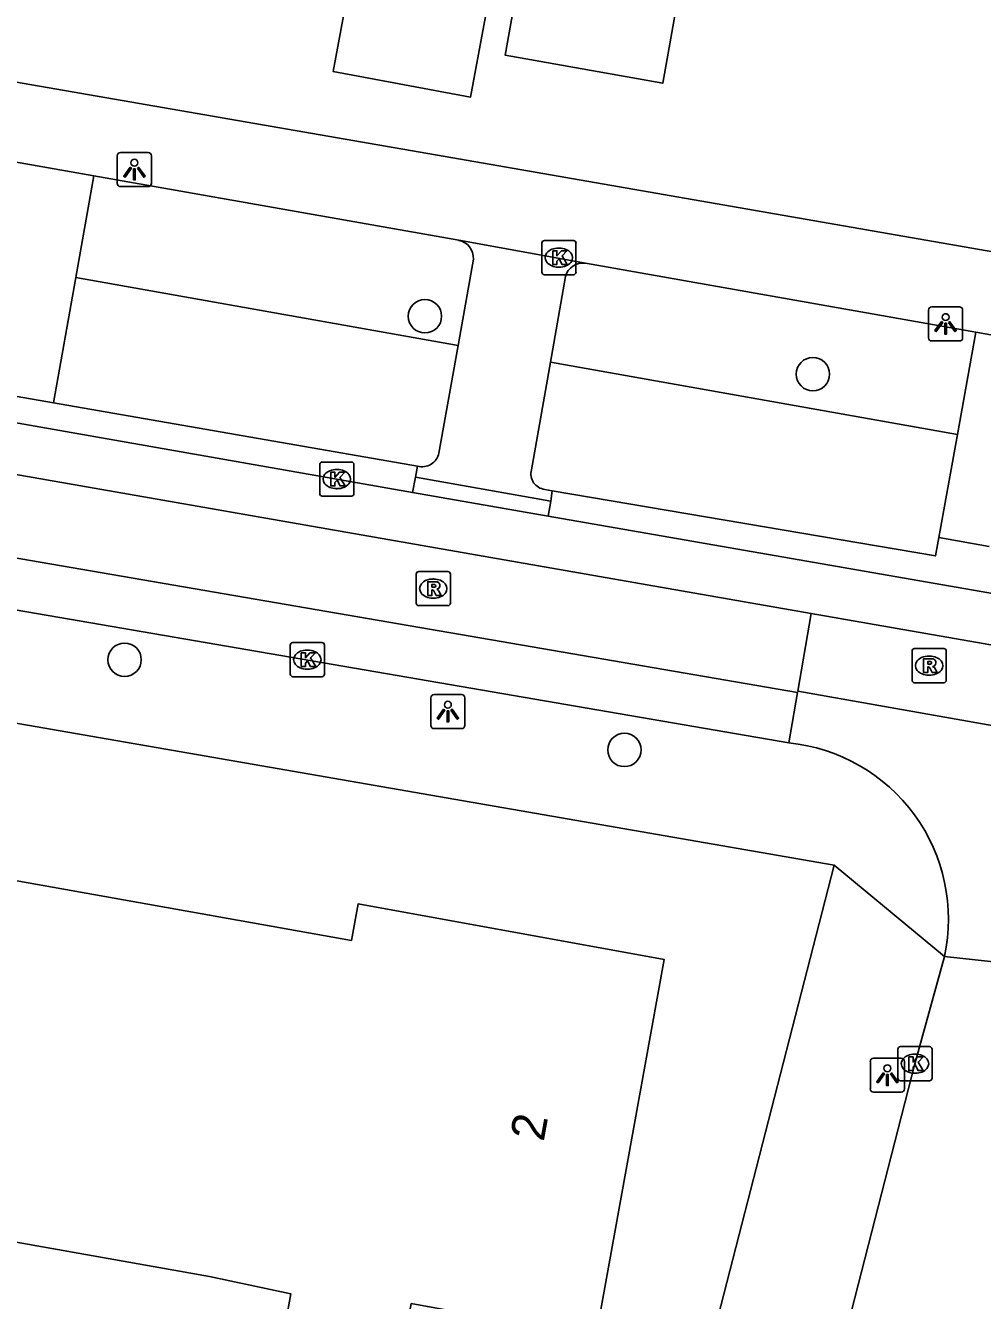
# Model space of a CAD drawing. Extents: x 163686 to 164493, y 382719 to 383870.
# Drawn here: x 163994.61 to 164022.62, y 383367.98 to 383405.27 of the extents above; entities that cross this region are included whole.
import ezdxf

# ---------------------------------------------------------------- set-up
doc = ezdxf.new("R2010")
doc.units = 0
for name, color, linetype in [('IMGEO_Boom', 7, 'Continuous'), ('IMGEO_Groenvoorziening', 7, 'Continuous'), ('IMGEO_Kolk', 7, 'Continuous'), ('IMGEO_Lichtpunt', 7, 'Continuous'), ('IMGEO_Pand', 7, 'Continuous'), ('IMGEO_Pand_nummerreeks', 7, 'Continuous'), ('IMGEO_Rijbaan_lokaal_open', 7, 'Continuous'), ('IMGEO_Rioolput', 7, 'Continuous'), ('IMGEO_Voetpad_open', 7, 'Continuous')]:
    doc.layers.add(name, color=color, linetype=linetype)

msp = doc.modelspace()

# ---------------------------------------------------------------- linework, layer by layer
at = {"layer": 'IMGEO_Boom'}
for centre in [(164006.301, 383396.766), (164017.654, 383395.071), (163997.512, 383386.717), (164012.139, 383384.08)]:
    msp.add_circle(centre, 0.489, dxfattribs=at)
at = {"layer": 'IMGEO_Groenvoorziening'}
for points in [[(163996.61, 383400.87), (163996.08, 383397.896)], [(163996.08, 383397.896), (163995.427, 383394.231)], [(164007.27, 383395.907), (163996.08, 383397.896)], [(164021.882, 383393.31), (164009.971, 383395.427)]]:
    msp.add_lwpolyline(points, dxfattribs=at)
at = {"layer": 'IMGEO_Kolk'}
for p, q in [((164009.72, 383398.055), (164009.72, 383398.907)), ((164009.795, 383398.981), (164010.647, 383398.981)), ((164010.721, 383398.907), (164010.721, 383398.055)), ((164010.208, 383398.761), (164010.233, 383398.761)), ((164010.231, 383398.201), (164010.206, 383398.201)), ((164010.647, 383397.981), (164009.795, 383397.981)), ((164003.298, 383392.502), (164004.15, 383392.502)), ((164003.223, 383391.576), (164003.223, 383392.428)), ((164003.711, 383392.282), (164003.736, 383392.282)), ((164004.224, 383392.428), (164004.224, 383391.576)), ((164004.15, 383391.502), (164003.298, 383391.502)), ((164003.734, 383391.722), (164003.709, 383391.722)), ((164002.359, 383386.295), (164002.359, 383387.147)), ((164002.434, 383387.221), (164003.286, 383387.221)), ((164002.847, 383387.001), (164002.872, 383387.001)), ((164003.36, 383387.147), (164003.36, 383386.295)), ((164003.286, 383386.221), (164002.434, 383386.221)), ((164002.87, 383386.441), (164002.845, 383386.441)), ((164020.14, 383374.476), (164020.14, 383375.328)), ((164020.215, 383375.402), (164021.067, 383375.402)), ((164021.141, 383375.328), (164021.141, 383374.476)), ((164020.628, 383375.182), (164020.653, 383375.182)), ((164020.651, 383374.622), (164020.626, 383374.622)), ((164021.067, 383374.402), (164020.215, 383374.402))]:
    msp.add_line(p, q, dxfattribs=at)
for points in [[(164009.72, 383398.055), (164009.72, 383398.907)], [(164009.795, 383398.981), (164010.647, 383398.981)], [(164010.721, 383398.907), (164010.721, 383398.055)], [(164010.041, 383398.681), (164010.164, 383398.681), (164010.164, 383398.53), (164010.294, 383398.681), (164010.458, 383398.681), (164010.312, 383398.53), (164010.465, 383398.281), (164010.313, 383398.281), (164010.228, 383398.445), (164010.164, 383398.378), (164010.164, 383398.281), (164010.041, 383398.281), (164010.041, 383398.681)], [(164010.647, 383397.981), (164009.795, 383397.981)], [(164003.298, 383392.502), (164004.15, 383392.502)], [(164003.223, 383391.576), (164003.223, 383392.428)], [(164003.544, 383392.202), (164003.667, 383392.202), (164003.667, 383392.051), (164003.797, 383392.202), (164003.961, 383392.202), (164003.815, 383392.051), (164003.968, 383391.802), (164003.816, 383391.802), (164003.731, 383391.966), (164003.667, 383391.899), (164003.667, 383391.802), (164003.544, 383391.802), (164003.544, 383392.202)], [(164004.224, 383392.428), (164004.224, 383391.576)], [(164004.15, 383391.502), (164003.298, 383391.502)], [(164002.359, 383386.295), (164002.359, 383387.147)], [(164002.434, 383387.221), (164003.286, 383387.221)], [(164002.68, 383386.921), (164002.803, 383386.921), (164002.803, 383386.77), (164002.933, 383386.921), (164003.097, 383386.921), (164002.951, 383386.77), (164003.104, 383386.521), (164002.952, 383386.521), (164002.867, 383386.685), (164002.803, 383386.618), (164002.803, 383386.521), (164002.68, 383386.521), (164002.68, 383386.921)], [(164003.36, 383387.147), (164003.36, 383386.295)], [(164003.286, 383386.221), (164002.434, 383386.221)], [(164020.14, 383374.476), (164020.14, 383375.328)], [(164020.215, 383375.402), (164021.067, 383375.402)], [(164021.141, 383375.328), (164021.141, 383374.476)], [(164020.461, 383375.102), (164020.584, 383375.102), (164020.584, 383374.951), (164020.714, 383375.102), (164020.878, 383375.102), (164020.732, 383374.951), (164020.885, 383374.702), (164020.733, 383374.702), (164020.648, 383374.866), (164020.584, 383374.799), (164020.584, 383374.702), (164020.461, 383374.702), (164020.461, 383375.102)], [(164021.067, 383374.402), (164020.215, 383374.402)]]:
    msp.add_lwpolyline(points, dxfattribs=at)
for centre, start, end in [((164009.797, 383398.905), 91.552, 178.448), ((164009.797, 383398.905), 91.552, 178.448), ((164010.645, 383398.905), 1.552, 88.448), ((164010.645, 383398.905), 1.552, 88.448), ((164009.797, 383398.057), 181.552, 268.448), ((164009.797, 383398.057), 181.552, 268.448), ((164010.645, 383398.057), 271.552, 358.448), ((164010.645, 383398.057), 271.552, 358.448), ((164003.3, 383392.426), 91.552, 178.448), ((164003.3, 383392.426), 91.552, 178.448), ((164004.148, 383392.426), 1.552, 88.448), ((164004.148, 383392.426), 1.552, 88.448), ((164003.3, 383391.578), 181.552, 268.448), ((164003.3, 383391.578), 181.552, 268.448), ((164004.148, 383391.578), 271.552, 358.448), ((164004.148, 383391.578), 271.552, 358.448), ((164002.436, 383387.145), 91.552, 178.448), ((164002.436, 383387.145), 91.552, 178.448), ((164003.284, 383387.145), 1.552, 88.448), ((164003.284, 383387.145), 1.552, 88.448), ((164002.436, 383386.297), 181.552, 268.448), ((164002.436, 383386.297), 181.552, 268.448), ((164003.284, 383386.297), 271.552, 358.448), ((164003.284, 383386.297), 271.552, 358.448), ((164020.217, 383375.326), 91.552, 178.448), ((164020.217, 383375.326), 91.552, 178.448), ((164021.065, 383375.326), 1.552, 88.448), ((164021.065, 383375.326), 1.552, 88.448), ((164020.217, 383374.478), 181.552, 268.448), ((164020.217, 383374.478), 181.552, 268.448), ((164021.065, 383374.478), 271.552, 358.448), ((164021.065, 383374.478), 271.552, 358.448)]:
    msp.add_arc(centre, 0.0765, start, end, dxfattribs=at)
for centre, major_axis, ratio, start_param, end_param in [((164010.207, 383398.481), (-0.387, 0.002), 0.722429, 4.712389, 7.853982), ((164010.232, 383398.481), (-0.39, 0.002), 0.717154, 1.570796, 4.712389), ((164003.71, 383392.002), (-0.387, 0.002), 0.722429, 4.712389, 7.853982), ((164003.735, 383392.002), (-0.39, 0.002), 0.717154, 1.570796, 4.712389), ((164002.846, 383386.721), (-0.387, 0.002), 0.722429, 4.712389, 7.853982), ((164002.871, 383386.721), (-0.39, 0.002), 0.717154, 1.570796, 4.712389), ((164020.627, 383374.902), (-0.387, 0.002), 0.722429, 4.712389, 7.853982), ((164020.652, 383374.902), (-0.39, 0.002), 0.717154, 1.570796, 4.712389)]:
    msp.add_ellipse(centre, major_axis=major_axis, ratio=ratio, start_param=start_param, end_param=end_param, dxfattribs=at)
at = {"layer": 'IMGEO_Lichtpunt'}
for p, q in [((163997.299, 383401.459), (163997.299, 383400.652)), ((163997.299, 383401.459), (163997.299, 383400.652)), ((163998.201, 383401.554), (163997.393, 383401.554)), ((163998.201, 383401.554), (163997.393, 383401.554)), ((163998.295, 383400.652), (163998.295, 383401.459)), ((163998.295, 383400.652), (163998.295, 383401.459)), ((163997.393, 383400.558), (163998.201, 383400.558)), ((163997.393, 383400.558), (163998.201, 383400.558)), ((164021.941, 383397.038), (164021.133, 383397.038)), ((164021.941, 383397.038), (164021.133, 383397.038)), ((164021.039, 383396.943), (164021.039, 383396.136)), ((164021.039, 383396.943), (164021.039, 383396.136)), ((164022.035, 383396.136), (164022.035, 383396.943)), ((164022.035, 383396.136), (164022.035, 383396.943)), ((164021.133, 383396.042), (164021.941, 383396.042)), ((164021.133, 383396.042), (164021.941, 383396.042)), ((164006.474, 383385.605), (164006.474, 383384.798)), ((164006.474, 383385.605), (164006.474, 383384.798)), ((164007.376, 383385.7), (164006.568, 383385.7)), ((164007.376, 383385.7), (164006.568, 383385.7)), ((164007.47, 383384.798), (164007.47, 383385.605)), ((164007.47, 383384.798), (164007.47, 383385.605)), ((164006.568, 383384.704), (164007.376, 383384.704)), ((164006.568, 383384.704), (164007.376, 383384.704)), ((164019.335, 383374.97), (164019.335, 383374.163)), ((164019.335, 383374.97), (164019.335, 383374.163)), ((164020.237, 383375.065), (164019.429, 383375.065)), ((164020.237, 383375.065), (164019.429, 383375.065)), ((164020.331, 383374.163), (164020.331, 383374.97)), ((164020.331, 383374.163), (164020.331, 383374.97)), ((164019.429, 383374.069), (164020.237, 383374.069)), ((164019.429, 383374.069), (164020.237, 383374.069))]:
    msp.add_line(p, q, dxfattribs=at)
for points in [[(163997.673, 383401.123), (163997.712, 383401.095), (163997.524, 383400.833), (163997.486, 383400.86), (163997.673, 383401.123)], [(163997.775, 383401.075), (163997.822, 383401.075), (163997.822, 383400.753), (163997.775, 383400.753), (163997.775, 383401.075)], [(163997.885, 383401.095), (163997.923, 383401.122), (163998.11, 383400.86), (163998.071, 383400.832), (163997.885, 383401.095)], [(164021.413, 383396.607), (164021.452, 383396.579), (164021.264, 383396.317), (164021.226, 383396.344), (164021.413, 383396.607)], [(164021.625, 383396.579), (164021.663, 383396.606), (164021.85, 383396.344), (164021.811, 383396.316), (164021.625, 383396.579)], [(164021.515, 383396.559), (164021.562, 383396.559), (164021.562, 383396.237), (164021.515, 383396.237), (164021.515, 383396.559)], [(164006.848, 383385.269), (164006.887, 383385.241), (164006.699, 383384.979), (164006.661, 383385.006), (164006.848, 383385.269)], [(164006.95, 383385.221), (164006.997, 383385.221), (164006.997, 383384.899), (164006.95, 383384.899), (164006.95, 383385.221)], [(164007.06, 383385.241), (164007.098, 383385.268), (164007.285, 383385.006), (164007.246, 383384.978), (164007.06, 383385.241)], [(164019.709, 383374.634), (164019.748, 383374.606), (164019.56, 383374.344), (164019.522, 383374.371), (164019.709, 383374.634)], [(164019.811, 383374.586), (164019.858, 383374.586), (164019.858, 383374.264), (164019.811, 383374.264), (164019.811, 383374.586)], [(164019.921, 383374.606), (164019.959, 383374.633), (164020.146, 383374.371), (164020.107, 383374.343), (164019.921, 383374.606)]]:
    msp.add_lwpolyline(points, dxfattribs=at)
for centre in [(163997.798, 383401.257), (164021.538, 383396.741), (164006.973, 383385.403), (164019.834, 383374.768)]:
    msp.add_circle(centre, 0.0994, dxfattribs=at)
for centre, start, end in [((163997.393, 383401.459), 90, 180), ((163997.393, 383401.459), 90, 180), ((163998.201, 383401.459), 0, 90), ((163998.201, 383401.459), 0, 90), ((163997.393, 383400.652), 180, 270), ((163997.393, 383400.652), 180, 270), ((163998.201, 383400.652), 270, 0), ((163998.201, 383400.652), 270, 360), ((164021.133, 383396.943), 90, 180), ((164021.133, 383396.943), 90, 180), ((164021.941, 383396.943), 0, 90), ((164021.941, 383396.943), 0, 90), ((164021.133, 383396.136), 180, 270), ((164021.133, 383396.136), 180, 270), ((164021.941, 383396.136), 270, 0), ((164021.941, 383396.136), 270, 360), ((164006.568, 383385.605), 90, 180), ((164006.568, 383385.605), 90, 180), ((164007.376, 383385.605), 0, 90), ((164007.376, 383385.605), 0, 90), ((164006.568, 383384.798), 180, 270), ((164006.568, 383384.798), 180, 270), ((164007.376, 383384.798), 270, 0), ((164007.376, 383384.798), 270, 360), ((164019.429, 383374.97), 90, 180), ((164019.429, 383374.97), 90, 180), ((164020.237, 383374.97), 0, 90), ((164020.237, 383374.97), 0, 90), ((164019.429, 383374.163), 180, 270), ((164019.429, 383374.163), 180, 270), ((164020.237, 383374.163), 270, 0), ((164020.237, 383374.163), 270, 360)]:
    msp.add_arc(centre, 0.0946, start, end, dxfattribs=at)
at = {"layer": 'IMGEO_Pand'}
for points in [[(164009.118, 383411.151), (164007.636, 383403.177), (164003.615, 383403.925), (164005.097, 383411.898), (164009.118, 383411.151)], [(164010.412, 383411.857), (164014.598, 383411.112), (164013.258, 383403.58), (164008.65, 383404.4), (164009.99, 383411.932)], [(164004.166, 383351.59), (164008.003, 383356.115), (164005.977, 383361.773), (164004.827, 383361.982), (164005.899, 383367.885), (164011.3, 383366.904), (164013.306, 383377.946), (164004.344, 383379.574), (164004.15, 383378.51), (164000, 383379.25), (163968.205, 383384.916), (163966.514, 383377.418), (163968.292, 383377.103), (163967.81, 383374.388), (164000, 383368.676), (164002.373, 383368.173), (164001.369, 383362.647), (164000.101, 383362.877), (164000, 383362.755), (163996.192, 383358.165), (163998.224, 383352.639), (164000, 383352.325), (164004.166, 383351.59)]]:
    msp.add_lwpolyline(points, dxfattribs=at)
at = {"layer": 'IMGEO_Rijbaan_lokaal_open'}
for points in [[(164007.288, 383398.986), (164010.995, 383398.317)], [(164007.27, 383395.907), (164007.721, 383398.439)], [(164009.971, 383395.427), (164010.411, 383397.928)], [(164006.71, 383392.765), (164007.27, 383395.907)], [(163983.679, 383395.523), (164005.936, 383391.612)], [(164009.971, 383395.427), (164009.415, 383392.272)], [(164017.601, 383388.073), (163983.447, 383394.041)], [(164006.023, 383392.061), (164006.082, 383392.379)], [(164006.023, 383392.061), (164009.988, 383391.357)], [(163983.069, 383391.632), (164017.202, 383385.764), (164016.948, 383384.286)], [(164009.907, 383390.922), (164005.936, 383391.612)], [(164009.807, 383391.701), (164010.021, 383391.662)], [(164010.021, 383391.662), (164009.988, 383391.357)], [(164009.907, 383390.922), (164035.582, 383386.454)], [(164016.948, 383384.286), (163982.836, 383390.149)], [(164023.472, 383387.047), (164023.119, 383384.758), (164017.214, 383385.799), (164017.601, 383388.073)], [(164017.601, 383388.073), (164023.472, 383387.047)], [(164021.504, 383378.036), (164020.641, 383374.902), (164012.259, 383342.236), (164012.332, 383342.199), (164007.809, 383324.466), (164007.729, 383324.49), (164007.155, 383322.365)], [(164021.504, 383378.036), (164030.569, 383377.057)]]:
    msp.add_lwpolyline(points, dxfattribs=at)
for centre, radius, start, end in [((164007.187, 383398.461), 0.534, 357.616, 79.1136), ((164010.924, 383397.791), 0.531, 82.3072, 165.0276), ((164006.213, 383392.87), 0.508, 255.0446, 348.1093), ((164009.863, 383392.159), 0.462, 165.849, 263.0914), ((164016.441, 383379.131), 5.18, 347.7992, 84.3819)]:
    msp.add_arc(centre, radius, start, end, dxfattribs=at)
at = {"layer": 'IMGEO_Rioolput'}
for p, q in [((164006.044, 383388.374), (164006.044, 383389.226)), ((164006.119, 383389.3), (164006.971, 383389.3)), ((164007.045, 383389.226), (164007.045, 383388.374)), ((164006.532, 383389.08), (164006.557, 383389.08)), ((164006.555, 383388.52), (164006.53, 383388.52)), ((164006.971, 383388.3), (164006.119, 383388.3)), ((164020.556, 383386.12), (164020.556, 383386.972)), ((164020.631, 383387.046), (164021.483, 383387.046)), ((164021.557, 383386.972), (164021.557, 383386.12)), ((164021.044, 383386.826), (164021.069, 383386.826)), ((164021.067, 383386.266), (164021.042, 383386.266)), ((164021.483, 383386.046), (164020.631, 383386.046))]:
    msp.add_line(p, q, dxfattribs=at)
for points in [[(164006.044, 383388.374), (164006.044, 383389.226)], [(164006.119, 383389.3), (164006.971, 383389.3)], [(164007.045, 383389.226), (164007.045, 383388.374)], [(164006.633, 383388.998), (164006.381, 383389), (164006.381, 383388.6)], [(164006.381, 383388.6), (164006.505, 383388.6), (164006.505, 383388.762), (164006.516, 383388.762)], [(164006.559, 383388.919), (164006.505, 383388.919), (164006.505, 383388.838)], [(164006.505, 383388.838), (164006.557, 383388.838)], [(164006.563, 383388.733), (164006.634, 383388.6), (164006.774, 383388.6), (164006.709, 383388.726)], [(164006.971, 383388.3), (164006.119, 383388.3)], [(164020.556, 383386.12), (164020.556, 383386.972)], [(164020.631, 383387.046), (164021.483, 383387.046)], [(164021.557, 383386.972), (164021.557, 383386.12)], [(164021.145, 383386.744), (164020.893, 383386.746), (164020.893, 383386.346)], [(164020.893, 383386.346), (164021.017, 383386.346), (164021.017, 383386.508), (164021.028, 383386.508)], [(164021.071, 383386.665), (164021.017, 383386.665), (164021.017, 383386.584)], [(164021.017, 383386.584), (164021.069, 383386.584)], [(164021.075, 383386.479), (164021.146, 383386.346), (164021.286, 383386.346), (164021.221, 383386.472)], [(164021.483, 383386.046), (164020.631, 383386.046)]]:
    msp.add_lwpolyline(points, dxfattribs=at)
for centre, radius, start, end in [((164006.121, 383389.224), 0.0765, 91.552, 178.448), ((164006.121, 383389.224), 0.0765, 91.552, 178.448), ((164006.969, 383389.224), 0.0765, 1.552, 88.448), ((164006.969, 383389.224), 0.0765, 1.552, 88.448), ((164006.515, 383388.709), 0.0533, 26.0293, 88.6989), ((164006.541, 383389.027), 0.19, 274.7715, 282.9687), ((164006.565, 383388.823), 0.0964, 77.0061, 93.1865), ((164006.579, 383388.88), 0.0378, 276.6634, 79.6772), ((164006.632, 383388.888), 0.109, 350.3612, 89.416), ((164006.63, 383388.888), 0.112, 277.5842, 350.9817), ((164006.614, 383388.673), 0.108, 29.5134, 73.7905), ((164006.121, 383388.376), 0.0765, 181.552, 268.448), ((164006.121, 383388.376), 0.0765, 181.552, 268.448), ((164006.969, 383388.376), 0.0765, 271.552, 358.448), ((164006.969, 383388.376), 0.0765, 271.552, 358.448), ((164020.633, 383386.97), 0.0765, 91.552, 178.448), ((164020.633, 383386.97), 0.0765, 91.552, 178.448), ((164021.481, 383386.97), 0.0765, 1.552, 88.448), ((164021.481, 383386.97), 0.0765, 1.552, 88.448), ((164021.027, 383386.455), 0.0533, 26.0293, 88.6989), ((164021.053, 383386.773), 0.19, 274.7715, 282.9687), ((164021.077, 383386.569), 0.0964, 77.0061, 93.1865), ((164021.091, 383386.626), 0.0378, 276.6634, 79.6772), ((164021.144, 383386.634), 0.109, 350.3612, 89.416), ((164021.142, 383386.634), 0.112, 277.5842, 350.9817), ((164021.126, 383386.419), 0.108, 29.5134, 73.7905), ((164020.633, 383386.122), 0.0765, 181.552, 268.448), ((164020.633, 383386.122), 0.0765, 181.552, 268.448), ((164021.481, 383386.122), 0.0765, 271.552, 358.448), ((164021.481, 383386.122), 0.0765, 271.552, 358.448)]:
    msp.add_arc(centre, radius, start, end, dxfattribs=at)
for centre, major_axis, ratio, start_param, end_param in [((164006.531, 383388.8), (-0.387, 0.002), 0.722429, 4.712389, 7.853982), ((164006.556, 383388.8), (-0.39, 0.002), 0.717154, 1.570796, 4.712389), ((164021.043, 383386.546), (-0.387, 0.002), 0.722429, 4.712389, 7.853982), ((164021.068, 383386.546), (-0.39, 0.002), 0.717154, 1.570796, 4.712389)]:
    msp.add_ellipse(centre, major_axis=major_axis, ratio=ratio, start_param=start_param, end_param=end_param, dxfattribs=at)
at = {"layer": 'IMGEO_Voetpad_open'}
for points in [[(163980.269, 383406.063), (164007.343, 383401.357), (164037.265, 383396.156), (164037.516, 383398.029), (164044.837, 383438.931), (164047.484, 383452.969)], [(163979.901, 383403.818), (163996.61, 383400.87)], [(163996.61, 383400.87), (164007.288, 383398.986)], [(163917.712, 383398.152), (164018.273, 383380.708)], [(164010.995, 383398.317), (164022.422, 383396.301)], [(163995.427, 383394.231), (163981.422, 383396.666)], [(164022.422, 383396.301), (164021.882, 383393.31)], [(164022.422, 383396.301), (164023.851, 383396.048)], [(164006.082, 383392.379), (163995.427, 383394.231)], [(164021.882, 383393.31), (164021.337, 383390.29)], [(164005.936, 383391.612), (164006.023, 383392.061)], [(164009.988, 383391.357), (164009.907, 383390.922)], [(164021.337, 383390.29), (164021.24, 383389.754), (164010.021, 383391.662)], [(164022.813, 383390.035), (164021.337, 383390.29)], [(164018.273, 383380.708), (164008.149, 383341.36), (163971.121, 383347.881), (163959.506, 383350.535)], [(164018.273, 383380.708), (164021.504, 383378.036)]]:
    msp.add_lwpolyline(points, dxfattribs=at)

# ---------------------------------------------------------------- texts
at = {"layer": 'IMGEO_Pand_nummerreeks'}
msp.add_text('2', height=1, rotation=79.7034, dxfattribs=at).set_placement((164009.774, 383372.602))

doc.saveas('drawing.dxf')
